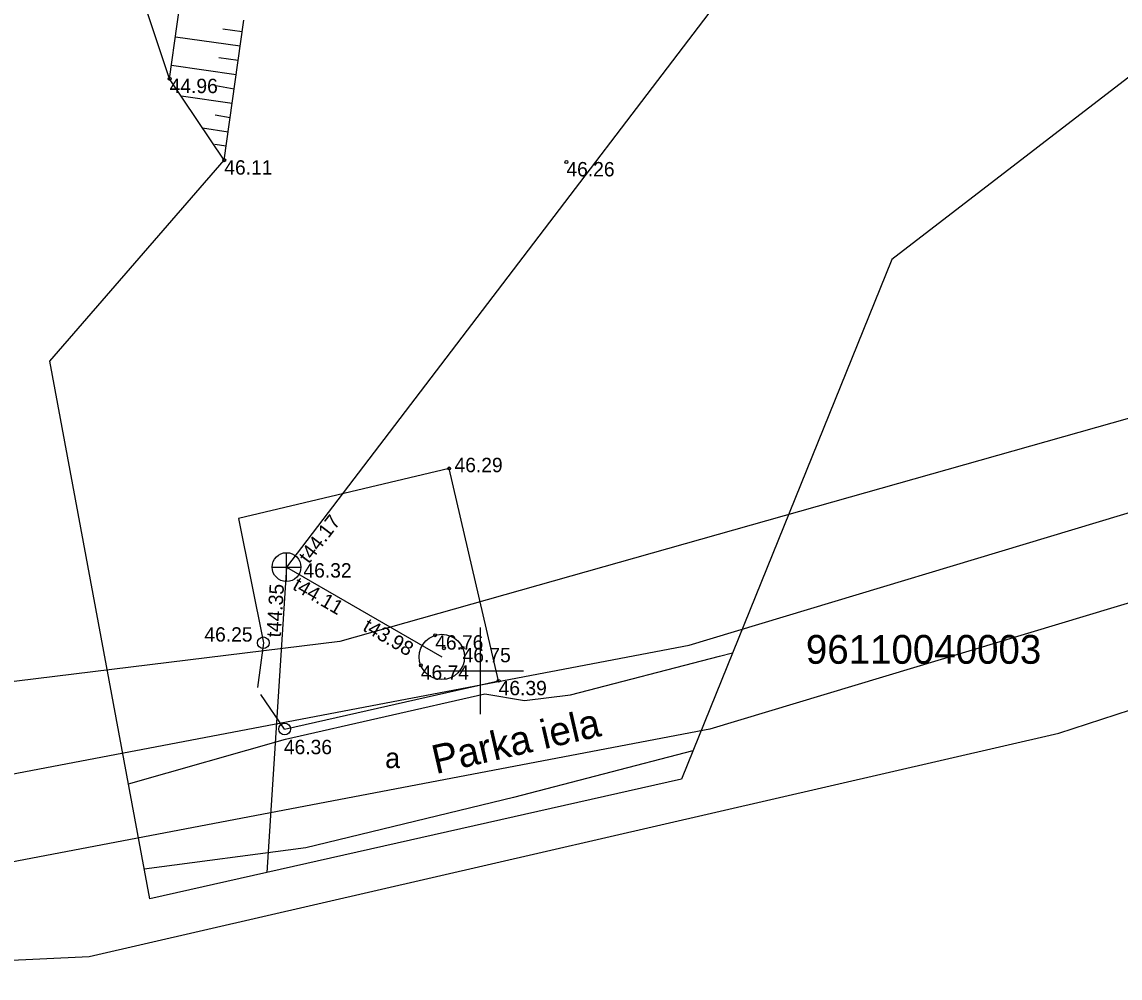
# Model space of a CAD drawing. Extents: x 561134 to 561329, y 413819 to 414116.
# Drawn here: x 561184.07 to 561222.24, y 413889.33 to 413922.54 of the extents above; entities that cross this region are included whole.
import ezdxf

# ---------------------------------------------------------------- set-up
doc = ezdxf.new("R2010")
doc.units = 0
for name, color, linetype in [('BUVE_INZE_VEKT_####_#', 7, 'Continuous'), ('CELI_CMAL_####_####_#', 7, 'Continuous'), ('CELI_CSEG_####_TKST_#', 7, 'Continuous'), ('CELI_IELA_####_TKST_#', 7, 'Continuous'), ('GEOD_ELEM_####_####_#', 7, 'Continuous'), ('NORB_ELEM_####_####_#', 7, 'Continuous'), ('NORB_ZOGS_BARJ_####_#', 7, 'Continuous'), ('NORB_ZOGS_ZSTP_####_#', 7, 'Continuous'), ('RAMI_UZMR_####_####_#', 7, 'Continuous'), ('RELJ_AATZ_####_TKST_#', 7, 'Continuous'), ('RELJ_ELEM_####_####_#', 7, 'Continuous'), ('RELJ_NOGA_####_####_#', 7, 'Continuous'), ('RELJ_NOGL_####_####_#', 7, 'Continuous'), ('ROBZ_PROJ_####_TKST_#', 7, 'Continuous'), ('ROBZ_UZMR_####_####_#', 7, 'Continuous'), ('SKAN_DETV_SPDK_####_#', 7, 'Continuous'), ('SKAN_ELEM_####_####_#', 7, 'Continuous'), ('SKAN_ELEM_PAST_TKST_#', 7, 'Continuous'), ('SKAN_VADP_PAST_####_#', 7, 'Continuous'), ('SKAN_VADP_PAST_TKST_#', 7, 'Continuous')]:
    doc.layers.add(name, color=color, linetype=linetype)

msp = doc.modelspace()

# ---------------------------------------------------------------- linework, layer by layer
at = {"layer": 'BUVE_INZE_VEKT_####_#'}
for p, q in [((561207.261, 413900.89), (561273.063, 413920.725)), ((561274.707, 413918.088), (561207.976, 413897.972)), ((561180.588, 413895.819), (561207.261, 413900.89)), ((561207.976, 413897.972), (561180.938, 413892.832))]:
    msp.add_line(p, q, dxfattribs=at)
at = {"layer": 'CELI_CMAL_####_####_#'}
for points in [[(561200.161, 413899.206), (561201.538, 413898.975), (561203.132, 413899.168), (561208.313, 413900.506), (561208.768, 413900.623)], [(561193.233, 413897.626), (561200.161, 413899.206)], [(561187.77, 413896.072), (561193.233, 413897.626)], [(561207.388, 413897.216), (561201.161, 413895.596), (561193.934, 413893.853), (561188.32, 413893.113)]]:
    msp.add_lwpolyline(points, dxfattribs=at)
at = {"layer": 'GEOD_ELEM_####_####_#'}
for p, q in [((561200, 413901.5), (561200, 413900)), ((561198.5, 413900), (561200, 413900)), ((561200, 413900), (561200, 413898.5)), ((561200, 413900), (561201.5, 413900))]:
    msp.add_line(p, q, dxfattribs=at)
at = {"layer": 'NORB_ELEM_####_####_#'}
for centre in [(561192.461, 413900.974), (561193.202, 413897.98)]:
    msp.add_circle(centre, 0.202, dxfattribs=at)
at = {"layer": 'NORB_ZOGS_BARJ_####_#'}
for p, q in [((561192.461, 413900.974), (561192.261, 413899.427)), ((561193.202, 413897.98), (561192.377, 413899.184))]:
    msp.add_line(p, q, dxfattribs=at)
at = {"layer": 'NORB_ZOGS_ZSTP_####_#'}
msp.add_lwpolyline([(561193.202, 413897.98), (561200.64, 413899.652), (561198.92, 413907.031), (561191.599, 413905.29), (561192.461, 413900.974)], dxfattribs=at)
at = {"layer": 'RAMI_UZMR_####_####_#'}
for points in [[(561188.512, 413892.082), (561185.041, 413910.753), (561191.104, 413917.736), (561189.205, 413920.568), (561187.984, 413924.22), (561187.954, 413928.121), (561192.417, 413932.029), (561202.582, 413934.262), (561206.983, 413936.681), (561215.453, 413945.229), (561216.519, 413946.905), (561218.27, 413950.393), (561229.69, 413964.77), (561237.253, 413982.653), (561235.655, 414013.737)], [(561254.18, 413993.826), (561250.885, 413973.719), (561248.352, 413955.204), (561242.331, 413942.835), (561241.508, 413940.241), (561240.647, 413938.452), (561234.45, 413929.795), (561214.305, 413914.287), (561206.991, 413896.237), (561188.512, 413892.082)]]:
    msp.add_lwpolyline(points, dxfattribs=at)
at = {"layer": 'RELJ_ELEM_####_####_#'}
for centre in [(561189.205, 413920.568), (561191.104, 413917.736), (561202.995, 413917.675), (561198.92, 413907.031), (561198.435, 413901.237), (561198.739, 413900.785), (561199.387, 413900.798), (561197.934, 413900.192), (561200.64, 413899.652)]:
    msp.add_circle(centre, 0.05, dxfattribs=at)
at = {"layer": 'RELJ_NOGA_####_####_#'}
for p, q in [((561191.728, 413922.193), (561191.052, 413922.287)), ((561191.658, 413921.697), (561189.406, 413922.013)), ((561191.589, 413921.202), (561190.913, 413921.297)), ((561191.52, 413920.707), (561189.268, 413921.022)), ((561190.807, 413920.335), (561191.45, 413920.212)), ((561189.606, 413919.971), (561191.38, 413919.717)), ((561190.789, 413919.309), (561191.312, 413919.222)), ((561190.352, 413918.857), (561191.242, 413918.726)), ((561190.773, 413918.291), (561191.173, 413918.231))]:
    msp.add_line(p, q, dxfattribs=at)
msp.add_lwpolyline([(561191.104, 413917.736), (561191.774, 413922.522), (561191.787, 413922.607)], dxfattribs=at)
at = {"layer": 'RELJ_NOGL_####_####_#'}
msp.add_lwpolyline([(561189.205, 413920.568), (561189.733, 413924.374)], dxfattribs=at)
at = {"layer": 'ROBZ_UZMR_####_####_#'}
for p, q in [((561270.72, 413922.391), (561195.123, 413901.021)), ((561220.114, 413897.841), (561277.05, 413916.422)), ((561195.123, 413901.021), (561175.113, 413898.572)), ((561186.413, 413890.079), (561220.114, 413897.841)), ((561170.117, 413889.33), (561186.413, 413890.079))]:
    msp.add_line(p, q, dxfattribs=at)
at = {"layer": 'SKAN_DETV_SPDK_####_#'}
msp.add_circle((561198.665, 413900.484), 0.787, dxfattribs=at)
at = {"layer": 'SKAN_ELEM_####_####_#'}
for p, q in [((561193.267, 413903.104), (561193.267, 413904.104)), ((561192.767, 413903.604), (561193.767, 413903.604))]:
    msp.add_line(p, q, dxfattribs=at)
msp.add_circle((561193.267, 413903.604), 0.5, dxfattribs=at)
at = {"layer": 'SKAN_VADP_PAST_####_#'}
for points in [[(561215.454, 413932.7), (561193.267, 413903.604)], [(561193.267, 413903.604), (561192.586, 413892.998)], [(561193.267, 413903.604), (561198.665, 413900.484)]]:
    msp.add_lwpolyline(points, dxfattribs=at)

# ---------------------------------------------------------------- texts
at = {"layer": 'CELI_CSEG_####_TKST_#'}
msp.add_text('a', height=0.7, dxfattribs=at).set_placement((561196.694, 413896.623))
at = {"layer": 'CELI_IELA_####_TKST_#'}
msp.add_text('Parka iela', height=1, rotation=12.9702, dxfattribs=at).set_placement((561198.453, 413896.41))
at = {"layer": 'RELJ_AATZ_####_TKST_#'}
for s, p in [('44.96', (561189.205, 413920.068)), ('46.11', (561191.104, 413917.236)), ('46.26', (561202.995, 413917.175)), ('46.29', (561199.105, 413906.901)), ('46.25', (561190.412, 413901.015)), ('46.76', (561198.435, 413900.737)), ('46.75', (561199.387, 413900.298)), ('46.74', (561197.934, 413899.692)), ('46.39', (561200.64, 413899.152)), ('46.36', (561193.174, 413897.105))]:
    msp.add_text(s, height=0.5, dxfattribs=at).set_placement(p)
at = {"layer": 'ROBZ_PROJ_####_TKST_#'}
msp.add_text('96110040003', height=1, dxfattribs=at).set_placement((561211.318, 413900.246))
at = {"layer": 'SKAN_ELEM_PAST_TKST_#'}
msp.add_text('46.32', height=0.5, dxfattribs=at).set_placement((561193.855, 413903.24))
at = {"layer": 'SKAN_VADP_PAST_TKST_#'}
for s, rotation, p in [('t44.17', 52.6729, (561194.045, 413903.694)), ('t44.11', 329.9735, (561193.441, 413902.853)), ('t44.35', 86.3246, (561193.063, 413901.151)), ('t43.98', 329.9735, (561195.882, 413901.421))]:
    msp.add_text(s, height=0.5, rotation=rotation, dxfattribs=at).set_placement(p)

doc.saveas('drawing.dxf')
